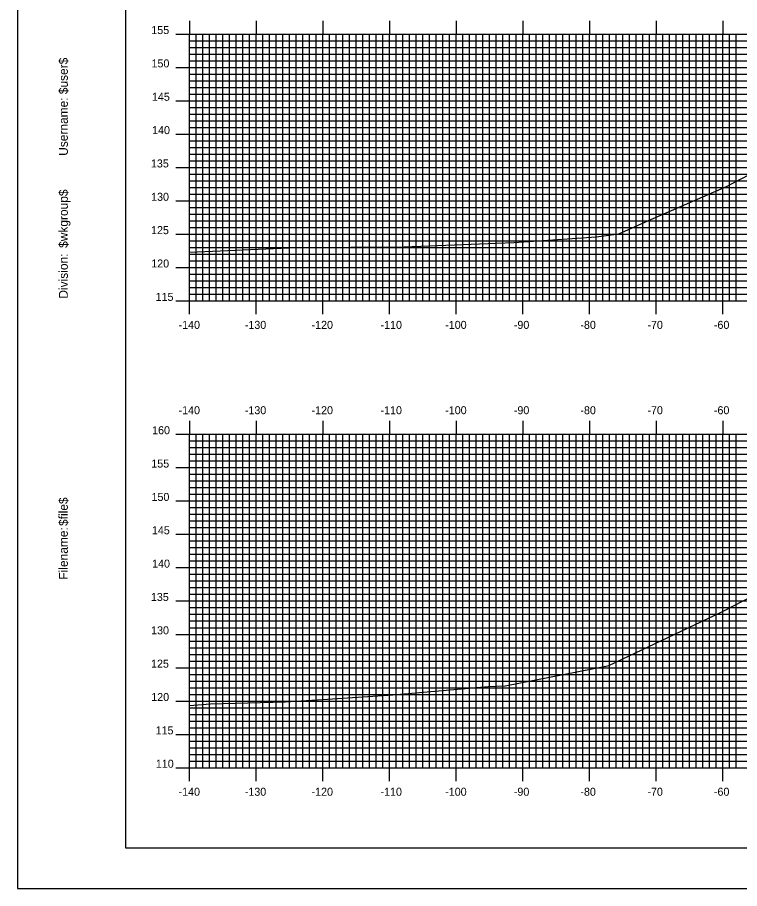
# Model space of a CAD drawing. Extents: x 851360 to 851703, y 364661 to 364881.
# Drawn here: x 851359.9 to 851468.2, y 364661.3 to 364791.9 of the extents above; entities that cross this region are included whole.
import ezdxf

# ---------------------------------------------------------------- set-up
doc = ezdxf.new("R2010")
doc.units = 0
for name, color, linetype in [('BORDER', 7, 'Continuous'), ('H_V ANNOTATION', 7, 'Continuous'), ('MAJOR', 7, 'Continuous'), ('MINOR', 7, 'Continuous'), ('PLOT BOUNDARY', 7, 'Continuous'), ('S_Roadway_Centerline', 7, 'Continuous')]:
    doc.layers.add(name, color=color, linetype=linetype)

msp = doc.modelspace()

# ---------------------------------------------------------------- linework, layer by layer
at = {"layer": 'BORDER'}
msp.add_lwpolyline([(851376.13, 364667.37), (851696.13, 364667.37), (851696.13, 364877.37), (851376.13, 364877.37)], close=True, dxfattribs=at)
at = {"layer": 'MAJOR'}
for p, q in [((851385.73, 364791.37), (851385.73, 364789.37)), ((851395.73, 364791.37), (851395.73, 364789.37)), ((851405.73, 364791.37), (851405.73, 364789.37)), ((851415.73, 364791.37), (851415.73, 364789.37)), ((851425.73, 364791.37), (851425.73, 364789.37)), ((851435.73, 364791.37), (851435.73, 364789.37)), ((851445.73, 364791.37), (851445.73, 364789.37)), ((851455.73, 364791.37), (851455.73, 364789.37)), ((851465.73, 364791.37), (851465.73, 364789.37)), ((851383.72, 364789.37), (851385.73, 364789.37)), ((851385.73, 364789.37), (851665.73, 364789.37)), ((851385.73, 364749.37), (851385.73, 364789.37)), ((851385.73, 364749.37), (851385.73, 364789.37)), ((851385.73, 364789.37), (851665.73, 364789.37)), ((851395.73, 364749.37), (851395.73, 364789.37)), ((851405.73, 364749.37), (851405.73, 364789.37)), ((851415.73, 364749.37), (851415.73, 364789.37)), ((851425.73, 364749.37), (851425.73, 364789.37)), ((851435.73, 364749.37), (851435.73, 364789.37)), ((851445.73, 364749.37), (851445.73, 364789.37)), ((851455.73, 364749.37), (851455.73, 364789.37)), ((851465.73, 364749.37), (851465.73, 364789.37)), ((851383.72, 364784.37), (851385.73, 364784.37)), ((851385.73, 364784.37), (851665.73, 364784.37)), ((851383.72, 364779.37), (851385.73, 364779.37)), ((851385.73, 364779.37), (851665.73, 364779.37)), ((851383.72, 364774.37), (851385.73, 364774.37)), ((851385.73, 364774.37), (851665.73, 364774.37)), ((851383.72, 364769.37), (851385.73, 364769.37)), ((851385.73, 364769.37), (851665.73, 364769.37)), ((851383.72, 364764.37), (851385.73, 364764.37)), ((851385.73, 364764.37), (851665.73, 364764.37)), ((851383.72, 364759.37), (851385.73, 364759.37)), ((851385.73, 364759.37), (851665.73, 364759.37)), ((851383.72, 364754.37), (851385.73, 364754.37)), ((851385.73, 364754.37), (851665.73, 364754.37)), ((851383.72, 364749.37), (851385.73, 364749.37)), ((851385.73, 364749.37), (851665.73, 364749.37)), ((851385.73, 364749.37), (851665.73, 364749.37)), ((851385.73, 364747.37), (851385.73, 364749.37)), ((851395.73, 364747.37), (851395.73, 364749.37)), ((851405.73, 364747.37), (851405.73, 364749.37)), ((851415.73, 364747.37), (851415.73, 364749.37)), ((851425.73, 364747.37), (851425.73, 364749.37)), ((851435.73, 364747.37), (851435.73, 364749.37)), ((851445.73, 364747.37), (851445.73, 364749.37)), ((851455.73, 364747.37), (851455.73, 364749.37)), ((851465.73, 364747.37), (851465.73, 364749.37)), ((851385.73, 364731.37), (851385.73, 364729.37)), ((851395.73, 364731.37), (851395.73, 364729.37)), ((851405.73, 364731.37), (851405.73, 364729.37)), ((851415.73, 364731.37), (851415.73, 364729.37)), ((851425.73, 364731.37), (851425.73, 364729.37)), ((851435.73, 364731.37), (851435.73, 364729.37)), ((851445.73, 364731.37), (851445.73, 364729.37)), ((851455.73, 364731.37), (851455.73, 364729.37)), ((851465.73, 364731.37), (851465.73, 364729.37)), ((851383.72, 364729.37), (851385.73, 364729.37)), ((851385.73, 364729.37), (851665.73, 364729.37)), ((851385.73, 364679.37), (851385.73, 364729.37)), ((851385.73, 364679.37), (851385.73, 364729.37)), ((851385.73, 364729.37), (851665.73, 364729.37)), ((851395.73, 364679.37), (851395.73, 364729.37)), ((851405.73, 364679.37), (851405.73, 364729.37)), ((851415.73, 364679.37), (851415.73, 364729.37)), ((851425.73, 364679.37), (851425.73, 364729.37)), ((851435.73, 364679.37), (851435.73, 364729.37)), ((851445.73, 364679.37), (851445.73, 364729.37)), ((851455.73, 364679.37), (851455.73, 364729.37)), ((851465.73, 364679.37), (851465.73, 364729.37)), ((851383.72, 364724.37), (851385.73, 364724.37)), ((851385.73, 364724.37), (851665.73, 364724.37)), ((851383.72, 364719.37), (851385.73, 364719.37)), ((851385.73, 364719.37), (851665.73, 364719.37)), ((851383.72, 364714.37), (851385.73, 364714.37)), ((851385.73, 364714.37), (851665.73, 364714.37)), ((851383.72, 364709.37), (851385.73, 364709.37)), ((851385.73, 364709.37), (851665.73, 364709.37)), ((851383.72, 364704.37), (851385.73, 364704.37)), ((851385.73, 364704.37), (851665.73, 364704.37)), ((851383.72, 364699.37), (851385.73, 364699.37)), ((851385.73, 364699.37), (851665.73, 364699.37)), ((851383.72, 364694.37), (851385.73, 364694.37)), ((851385.73, 364694.37), (851665.73, 364694.37)), ((851383.72, 364689.37), (851385.73, 364689.37)), ((851385.73, 364689.37), (851665.73, 364689.37)), ((851383.72, 364684.37), (851385.73, 364684.37)), ((851385.73, 364684.37), (851665.73, 364684.37)), ((851383.72, 364679.37), (851385.73, 364679.37)), ((851385.73, 364679.37), (851665.73, 364679.37)), ((851385.73, 364679.37), (851665.73, 364679.37)), ((851385.73, 364677.37), (851385.73, 364679.37)), ((851395.73, 364677.37), (851395.73, 364679.37)), ((851405.73, 364677.37), (851405.73, 364679.37)), ((851415.73, 364677.37), (851415.73, 364679.37)), ((851425.73, 364677.37), (851425.73, 364679.37)), ((851435.73, 364677.37), (851435.73, 364679.37)), ((851445.73, 364677.37), (851445.73, 364679.37)), ((851455.73, 364677.37), (851455.73, 364679.37)), ((851465.73, 364677.37), (851465.73, 364679.37))]:
    msp.add_line(p, q, dxfattribs=at)
at = {"layer": 'MINOR'}
for p, q in [((851385.73, 364788.37), (851665.73, 364788.37)), ((851385.73, 364788.37), (851387.73, 364788.37)), ((851386.73, 364749.37), (851386.73, 364789.37)), ((851387.73, 364749.37), (851387.73, 364789.37)), ((851388.73, 364749.37), (851388.73, 364789.37)), ((851389.73, 364749.37), (851389.73, 364789.37)), ((851390.73, 364749.37), (851390.73, 364789.37)), ((851391.73, 364749.37), (851391.73, 364789.37)), ((851392.73, 364749.37), (851392.73, 364789.37)), ((851393.73, 364749.37), (851393.73, 364789.37)), ((851394.73, 364749.37), (851394.73, 364789.37)), ((851396.73, 364749.37), (851396.73, 364789.37)), ((851397.73, 364749.37), (851397.73, 364789.37)), ((851398.73, 364749.37), (851398.73, 364789.37)), ((851399.73, 364749.37), (851399.73, 364789.37)), ((851400.73, 364749.37), (851400.73, 364789.37)), ((851401.73, 364749.37), (851401.73, 364789.37)), ((851402.73, 364749.37), (851402.73, 364789.37)), ((851403.73, 364749.37), (851403.73, 364789.37)), ((851404.73, 364749.37), (851404.73, 364789.37)), ((851406.73, 364749.37), (851406.73, 364789.37)), ((851407.73, 364749.37), (851407.73, 364789.37)), ((851408.73, 364749.37), (851408.73, 364789.37)), ((851409.73, 364749.37), (851409.73, 364789.37)), ((851410.73, 364749.37), (851410.73, 364789.37)), ((851411.73, 364749.37), (851411.73, 364789.37)), ((851412.73, 364749.37), (851412.73, 364789.37)), ((851413.73, 364749.37), (851413.73, 364789.37)), ((851414.73, 364749.37), (851414.73, 364789.37)), ((851416.73, 364749.37), (851416.73, 364789.37)), ((851417.73, 364749.37), (851417.73, 364789.37)), ((851418.73, 364749.37), (851418.73, 364789.37)), ((851419.73, 364749.37), (851419.73, 364789.37)), ((851420.73, 364749.37), (851420.73, 364789.37)), ((851421.73, 364749.37), (851421.73, 364789.37)), ((851422.73, 364749.37), (851422.73, 364789.37)), ((851423.73, 364749.37), (851423.73, 364789.37)), ((851424.73, 364749.37), (851424.73, 364789.37)), ((851426.73, 364749.37), (851426.73, 364789.37)), ((851427.73, 364749.37), (851427.73, 364789.37)), ((851428.73, 364749.37), (851428.73, 364789.37)), ((851429.73, 364749.37), (851429.73, 364789.37)), ((851430.73, 364749.37), (851430.73, 364789.37)), ((851431.73, 364749.37), (851431.73, 364789.37)), ((851432.73, 364749.37), (851432.73, 364789.37)), ((851433.73, 364749.37), (851433.73, 364789.37)), ((851434.73, 364749.37), (851434.73, 364789.37)), ((851436.73, 364749.37), (851436.73, 364789.37)), ((851437.73, 364749.37), (851437.73, 364789.37)), ((851438.73, 364749.37), (851438.73, 364789.37)), ((851439.73, 364749.37), (851439.73, 364789.37)), ((851440.73, 364749.37), (851440.73, 364789.37)), ((851441.73, 364749.37), (851441.73, 364789.37)), ((851442.73, 364749.37), (851442.73, 364789.37)), ((851443.73, 364749.37), (851443.73, 364789.37)), ((851444.73, 364749.37), (851444.73, 364789.37)), ((851446.73, 364749.37), (851446.73, 364789.37)), ((851447.73, 364749.37), (851447.73, 364789.37)), ((851448.73, 364749.37), (851448.73, 364789.37)), ((851449.73, 364749.37), (851449.73, 364789.37)), ((851450.73, 364749.37), (851450.73, 364789.37)), ((851451.73, 364749.37), (851451.73, 364789.37)), ((851452.73, 364749.37), (851452.73, 364789.37)), ((851453.73, 364749.37), (851453.73, 364789.37)), ((851454.73, 364749.37), (851454.73, 364789.37)), ((851456.73, 364749.37), (851456.73, 364789.37)), ((851457.73, 364749.37), (851457.73, 364789.37)), ((851458.73, 364749.37), (851458.73, 364789.37)), ((851459.73, 364749.37), (851459.73, 364789.37)), ((851460.73, 364749.37), (851460.73, 364789.37)), ((851461.73, 364749.37), (851461.73, 364789.37)), ((851462.73, 364749.37), (851462.73, 364789.37)), ((851463.73, 364749.37), (851463.73, 364789.37)), ((851464.73, 364749.37), (851464.73, 364789.37)), ((851466.73, 364749.37), (851466.73, 364789.37)), ((851467.73, 364749.37), (851467.73, 364789.37)), ((851385.73, 364787.37), (851665.73, 364787.37)), ((851385.73, 364787.37), (851387.73, 364787.37)), ((851385.73, 364786.37), (851665.73, 364786.37)), ((851385.73, 364786.37), (851387.73, 364786.37)), ((851385.73, 364785.37), (851665.73, 364785.37)), ((851385.73, 364785.37), (851387.73, 364785.37)), ((851385.73, 364783.37), (851665.73, 364783.37)), ((851385.73, 364783.37), (851387.73, 364783.37)), ((851385.73, 364782.37), (851665.73, 364782.37)), ((851385.73, 364782.37), (851387.73, 364782.37)), ((851385.73, 364781.37), (851665.73, 364781.37)), ((851385.73, 364781.37), (851387.73, 364781.37)), ((851385.73, 364780.37), (851665.73, 364780.37)), ((851385.73, 364780.37), (851387.73, 364780.37)), ((851385.73, 364778.37), (851665.73, 364778.37)), ((851385.73, 364778.37), (851387.73, 364778.37)), ((851385.73, 364777.37), (851665.73, 364777.37)), ((851385.73, 364777.37), (851387.73, 364777.37)), ((851385.73, 364776.37), (851665.73, 364776.37)), ((851385.73, 364776.37), (851387.73, 364776.37)), ((851385.73, 364775.37), (851665.73, 364775.37)), ((851385.73, 364775.37), (851387.73, 364775.37)), ((851385.73, 364773.37), (851665.73, 364773.37)), ((851385.73, 364773.37), (851387.73, 364773.37)), ((851385.73, 364772.37), (851665.73, 364772.37)), ((851385.73, 364772.37), (851387.73, 364772.37)), ((851385.73, 364771.37), (851665.73, 364771.37)), ((851385.73, 364771.37), (851387.73, 364771.37)), ((851385.73, 364770.37), (851665.73, 364770.37)), ((851385.73, 364770.37), (851387.73, 364770.37)), ((851385.73, 364768.37), (851665.73, 364768.37)), ((851385.73, 364768.37), (851387.73, 364768.37)), ((851385.73, 364767.37), (851665.73, 364767.37)), ((851385.73, 364767.37), (851387.73, 364767.37)), ((851385.73, 364766.37), (851665.73, 364766.37)), ((851385.73, 364766.37), (851387.73, 364766.37)), ((851385.73, 364765.37), (851665.73, 364765.37)), ((851385.73, 364765.37), (851387.73, 364765.37)), ((851385.73, 364763.37), (851665.73, 364763.37)), ((851385.73, 364763.37), (851387.73, 364763.37)), ((851385.73, 364762.37), (851665.73, 364762.37)), ((851385.73, 364762.37), (851387.73, 364762.37)), ((851385.73, 364761.37), (851665.73, 364761.37)), ((851385.73, 364761.37), (851387.73, 364761.37)), ((851385.73, 364760.37), (851665.73, 364760.37)), ((851385.73, 364760.37), (851387.73, 364760.37)), ((851385.73, 364758.37), (851665.73, 364758.37)), ((851385.73, 364758.37), (851387.73, 364758.37)), ((851385.73, 364757.37), (851665.73, 364757.37)), ((851385.73, 364757.37), (851387.73, 364757.37)), ((851385.73, 364756.37), (851665.73, 364756.37)), ((851385.73, 364756.37), (851387.73, 364756.37)), ((851385.73, 364755.37), (851665.73, 364755.37)), ((851385.73, 364755.37), (851387.73, 364755.37)), ((851385.73, 364753.37), (851665.73, 364753.37)), ((851385.73, 364753.37), (851387.73, 364753.37)), ((851385.73, 364752.37), (851665.73, 364752.37)), ((851385.73, 364752.37), (851387.73, 364752.37)), ((851385.73, 364751.37), (851665.73, 364751.37)), ((851385.73, 364751.37), (851387.73, 364751.37)), ((851385.73, 364750.37), (851665.73, 364750.37)), ((851385.73, 364750.37), (851387.73, 364750.37)), ((851385.73, 364728.37), (851665.73, 364728.37)), ((851385.73, 364728.37), (851387.73, 364728.37)), ((851386.73, 364679.37), (851386.73, 364729.37)), ((851387.73, 364679.37), (851387.73, 364729.37)), ((851388.73, 364679.37), (851388.73, 364729.37)), ((851389.73, 364679.37), (851389.73, 364729.37)), ((851390.73, 364679.37), (851390.73, 364729.37)), ((851391.73, 364679.37), (851391.73, 364729.37)), ((851392.73, 364679.37), (851392.73, 364729.37)), ((851393.73, 364679.37), (851393.73, 364729.37)), ((851394.73, 364679.37), (851394.73, 364729.37)), ((851396.73, 364679.37), (851396.73, 364729.37)), ((851397.73, 364679.37), (851397.73, 364729.37)), ((851398.73, 364679.37), (851398.73, 364729.37)), ((851399.73, 364679.37), (851399.73, 364729.37)), ((851400.73, 364679.37), (851400.73, 364729.37)), ((851401.73, 364679.37), (851401.73, 364729.37)), ((851402.73, 364679.37), (851402.73, 364729.37)), ((851403.73, 364679.37), (851403.73, 364729.37)), ((851404.73, 364679.37), (851404.73, 364729.37)), ((851406.73, 364679.37), (851406.73, 364729.37)), ((851407.73, 364679.37), (851407.73, 364729.37)), ((851408.73, 364679.37), (851408.73, 364729.37)), ((851409.73, 364679.37), (851409.73, 364729.37)), ((851410.73, 364679.37), (851410.73, 364729.37)), ((851411.73, 364679.37), (851411.73, 364729.37)), ((851412.73, 364679.37), (851412.73, 364729.37)), ((851413.73, 364679.37), (851413.73, 364729.37)), ((851414.73, 364679.37), (851414.73, 364729.37)), ((851416.73, 364679.37), (851416.73, 364729.37)), ((851417.73, 364679.37), (851417.73, 364729.37)), ((851418.73, 364679.37), (851418.73, 364729.37)), ((851419.73, 364679.37), (851419.73, 364729.37)), ((851420.73, 364679.37), (851420.73, 364729.37)), ((851421.73, 364679.37), (851421.73, 364729.37)), ((851422.73, 364679.37), (851422.73, 364729.37)), ((851423.73, 364679.37), (851423.73, 364729.37)), ((851424.73, 364679.37), (851424.73, 364729.37)), ((851426.73, 364679.37), (851426.73, 364729.37)), ((851427.73, 364679.37), (851427.73, 364729.37)), ((851428.73, 364679.37), (851428.73, 364729.37)), ((851429.73, 364679.37), (851429.73, 364729.37)), ((851430.73, 364679.37), (851430.73, 364729.37)), ((851431.73, 364679.37), (851431.73, 364729.37)), ((851432.73, 364679.37), (851432.73, 364729.37)), ((851433.73, 364679.37), (851433.73, 364729.37)), ((851434.73, 364679.37), (851434.73, 364729.37)), ((851436.73, 364679.37), (851436.73, 364729.37)), ((851437.73, 364679.37), (851437.73, 364729.37)), ((851438.73, 364679.37), (851438.73, 364729.37)), ((851439.73, 364679.37), (851439.73, 364729.37)), ((851440.73, 364679.37), (851440.73, 364729.37)), ((851441.73, 364679.37), (851441.73, 364729.37)), ((851442.73, 364679.37), (851442.73, 364729.37)), ((851443.73, 364679.37), (851443.73, 364729.37)), ((851444.73, 364679.37), (851444.73, 364729.37)), ((851446.73, 364679.37), (851446.73, 364729.37)), ((851447.73, 364679.37), (851447.73, 364729.37)), ((851448.73, 364679.37), (851448.73, 364729.37)), ((851449.73, 364679.37), (851449.73, 364729.37)), ((851450.73, 364679.37), (851450.73, 364729.37)), ((851451.73, 364679.37), (851451.73, 364729.37)), ((851452.73, 364679.37), (851452.73, 364729.37)), ((851453.73, 364679.37), (851453.73, 364729.37)), ((851454.73, 364679.37), (851454.73, 364729.37)), ((851456.73, 364679.37), (851456.73, 364729.37)), ((851457.73, 364679.37), (851457.73, 364729.37)), ((851458.73, 364679.37), (851458.73, 364729.37)), ((851459.73, 364679.37), (851459.73, 364729.37)), ((851460.73, 364679.37), (851460.73, 364729.37)), ((851461.73, 364679.37), (851461.73, 364729.37)), ((851462.73, 364679.37), (851462.73, 364729.37)), ((851463.73, 364679.37), (851463.73, 364729.37)), ((851464.73, 364679.37), (851464.73, 364729.37)), ((851466.73, 364679.37), (851466.73, 364729.37)), ((851467.73, 364679.37), (851467.73, 364729.37)), ((851385.73, 364727.37), (851665.73, 364727.37)), ((851385.73, 364727.37), (851387.73, 364727.37)), ((851385.73, 364726.37), (851665.73, 364726.37)), ((851385.73, 364726.37), (851387.73, 364726.37)), ((851385.73, 364725.37), (851665.73, 364725.37)), ((851385.73, 364725.37), (851387.73, 364725.37)), ((851385.73, 364723.37), (851665.73, 364723.37)), ((851385.73, 364723.37), (851387.73, 364723.37)), ((851385.73, 364722.37), (851665.73, 364722.37)), ((851385.73, 364722.37), (851387.73, 364722.37)), ((851385.73, 364721.37), (851665.73, 364721.37)), ((851385.73, 364721.37), (851387.73, 364721.37)), ((851385.73, 364720.37), (851665.73, 364720.37)), ((851385.73, 364720.37), (851387.73, 364720.37)), ((851385.73, 364718.37), (851665.73, 364718.37)), ((851385.73, 364718.37), (851387.73, 364718.37)), ((851385.73, 364717.37), (851665.73, 364717.37)), ((851385.73, 364717.37), (851387.73, 364717.37)), ((851385.73, 364716.37), (851665.73, 364716.37)), ((851385.73, 364716.37), (851387.73, 364716.37)), ((851385.73, 364715.37), (851665.73, 364715.37)), ((851385.73, 364715.37), (851387.73, 364715.37)), ((851385.73, 364713.37), (851665.73, 364713.37)), ((851385.73, 364713.37), (851387.73, 364713.37)), ((851385.73, 364712.37), (851665.73, 364712.37)), ((851385.73, 364712.37), (851387.73, 364712.37)), ((851385.73, 364711.37), (851665.73, 364711.37)), ((851385.73, 364711.37), (851387.73, 364711.37)), ((851385.73, 364710.37), (851665.73, 364710.37)), ((851385.73, 364710.37), (851387.73, 364710.37)), ((851385.73, 364708.37), (851665.73, 364708.37)), ((851385.73, 364708.37), (851387.73, 364708.37)), ((851385.73, 364707.37), (851665.73, 364707.37)), ((851385.73, 364707.37), (851387.73, 364707.37)), ((851385.73, 364706.37), (851665.73, 364706.37)), ((851385.73, 364706.37), (851387.73, 364706.37)), ((851385.73, 364705.37), (851665.73, 364705.37)), ((851385.73, 364705.37), (851387.73, 364705.37)), ((851385.73, 364703.37), (851665.73, 364703.37)), ((851385.73, 364703.37), (851387.73, 364703.37)), ((851385.73, 364702.37), (851665.73, 364702.37)), ((851385.73, 364702.37), (851387.73, 364702.37)), ((851385.73, 364701.37), (851665.73, 364701.37)), ((851385.73, 364701.37), (851387.73, 364701.37)), ((851385.73, 364700.37), (851665.73, 364700.37)), ((851385.73, 364700.37), (851387.73, 364700.37)), ((851385.73, 364698.37), (851665.73, 364698.37)), ((851385.73, 364698.37), (851387.73, 364698.37)), ((851385.73, 364697.37), (851665.73, 364697.37)), ((851385.73, 364697.37), (851387.73, 364697.37)), ((851385.73, 364696.37), (851665.73, 364696.37)), ((851385.73, 364696.37), (851387.73, 364696.37)), ((851385.73, 364695.37), (851665.73, 364695.37)), ((851385.73, 364695.37), (851387.73, 364695.37)), ((851385.73, 364693.37), (851665.73, 364693.37)), ((851385.73, 364693.37), (851387.73, 364693.37)), ((851385.73, 364692.37), (851665.73, 364692.37)), ((851385.73, 364692.37), (851387.73, 364692.37)), ((851385.73, 364691.37), (851665.73, 364691.37)), ((851385.73, 364691.37), (851387.73, 364691.37)), ((851385.73, 364690.37), (851665.73, 364690.37)), ((851385.73, 364690.37), (851387.73, 364690.37)), ((851385.73, 364688.37), (851665.73, 364688.37)), ((851385.73, 364688.37), (851387.73, 364688.37)), ((851385.73, 364687.37), (851665.73, 364687.37)), ((851385.73, 364687.37), (851387.73, 364687.37)), ((851385.73, 364686.37), (851665.73, 364686.37)), ((851385.73, 364686.37), (851387.73, 364686.37)), ((851385.73, 364685.37), (851665.73, 364685.37)), ((851385.73, 364685.37), (851387.73, 364685.37)), ((851385.73, 364683.37), (851665.73, 364683.37)), ((851385.73, 364683.37), (851387.73, 364683.37)), ((851385.73, 364682.37), (851665.73, 364682.37)), ((851385.73, 364682.37), (851387.73, 364682.37)), ((851385.73, 364681.37), (851665.73, 364681.37)), ((851385.73, 364681.37), (851387.73, 364681.37)), ((851385.73, 364680.37), (851665.73, 364680.37)), ((851385.73, 364680.37), (851387.73, 364680.37))]:
    msp.add_line(p, q, dxfattribs=at)
at = {"layer": 'PLOT BOUNDARY'}
msp.add_lwpolyline([(851359.94, 364661.25), (851699.94, 364661.25), (851699.94, 364881.25), (851359.94, 364881.25)], close=True, dxfattribs=at)
at = {"layer": 'S_Roadway_Centerline'}
for points in [[(851385.73, 364756.66), (851398.32, 364757.2), (851401.86, 364757.35), (851401.91, 364757.35), (851401.96, 364757.35), (851417.86, 364757.47), (851431.79, 364758.03), (851434.43, 364758.14), (851446.71, 364758.98), (851450.13, 364759.42), (851454.49, 364761.39), (851466.25, 364766.51), (851476.5, 364771.87), (851482.6, 364775.13), (851489.92, 364777.99)], [(851385.73, 364688.72), (851388.91, 364688.93), (851400.08, 364689.25), (851405.67, 364689.62), (851416.25, 364690.29), (851430.53, 364691.53), (851433.06, 364691.66), (851448.42, 364694.67), (851448.62, 364694.71), (851464.4, 364702.17), (851465.67, 364702.79), (851481.28, 364710.84), (851486.23, 364713.08), (851489.65, 364714.59)]]:
    msp.add_lwpolyline(points, dxfattribs=at)

# ---------------------------------------------------------------- texts
at = {"layer": 'BORDER'}
for s, p in [('$user$', (851367.5, 364780.35)), ('Username:', (851367.5, 364771.11)), ('$wkgroup$', (851367.5, 364757.31)), ('Division:', (851367.5, 364749.7)), ('$file$', (851367.5, 364715.62)), ('Filename:', (851367.5, 364707.57))]:
    msp.add_text(s, height=1.339, rotation=90, dxfattribs=at).set_placement(p)
at = {"layer": 'H_V ANNOTATION'}
for s, p in [('155', (851380.02, 364789.37)), ('150', (851380.05, 364784.37)), ('145', (851380.11, 364779.37)), ('140', (851380.14, 364774.37)), ('135', (851379.96, 364769.37)), ('130', (851379.99, 364764.37)), ('125', (851379.98, 364759.37)), ('120', (851380.01, 364754.37)), ('115', (851380.66, 364749.37)), ('-140', (851384.11, 364745.17)), ('-130', (851394.04, 364745.17)), ('-120', (851404.05, 364745.17)), ('-110', (851414.39, 364745.17)), ('-100', (851424.09, 364745.17)), ('-90', (851434.38, 364745.17)), ('-80', (851444.36, 364745.17)), ('-70', (851454.41, 364745.17)), ('-60', (851464.38, 364745.17)), ('-140', (851384.11, 364732.37)), ('-130', (851394.04, 364732.37)), ('-120', (851404.05, 364732.37)), ('-110', (851414.39, 364732.37)), ('-100', (851424.09, 364732.37)), ('-90', (851434.38, 364732.37)), ('-80', (851444.36, 364732.37)), ('-70', (851454.41, 364732.37)), ('-60', (851464.38, 364732.37)), ('160', (851380.14, 364729.37)), ('155', (851380.02, 364724.37)), ('150', (851380.05, 364719.37)), ('145', (851380.11, 364714.37)), ('140', (851380.14, 364709.37)), ('135', (851379.96, 364704.37)), ('130', (851379.99, 364699.37)), ('125', (851379.98, 364694.37)), ('120', (851380.01, 364689.37)), ('115', (851380.66, 364684.37)), ('110', (851380.7, 364679.37)), ('-140', (851384.11, 364675.17)), ('-130', (851394.04, 364675.17)), ('-120', (851404.05, 364675.17)), ('-110', (851414.39, 364675.17)), ('-100', (851424.09, 364675.17)), ('-90', (851434.38, 364675.17)), ('-80', (851444.36, 364675.17)), ('-70', (851454.41, 364675.17)), ('-60', (851464.38, 364675.17))]:
    msp.add_text(s, height=1.2, dxfattribs=at).set_placement(p)
at = {"layer": 'MAJOR'}
for p in [(851385.72, 364749.37), (851385.72, 364679.37)]:
    msp.add_text('-', height=0.012, dxfattribs=at).set_placement(p)

doc.saveas('drawing.dxf')
